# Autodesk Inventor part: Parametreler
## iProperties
Created: 2005-04
Part Number: Parametreler
Document SubType Name: Modeling
Designer: Admin
Density: 1 g/cm^3
Thickness: 20.000 mm
Height: 500.000 mm
d0: 300.000 mm
Author: Admin
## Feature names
1. Extrusion1
2. Extrusion2
3. Extrusion3
4. Extrusion4
5. Hole1-Index
6. MidHole [Hole]
7. Rectangular Pattern1
8. Rectangular Pattern2
